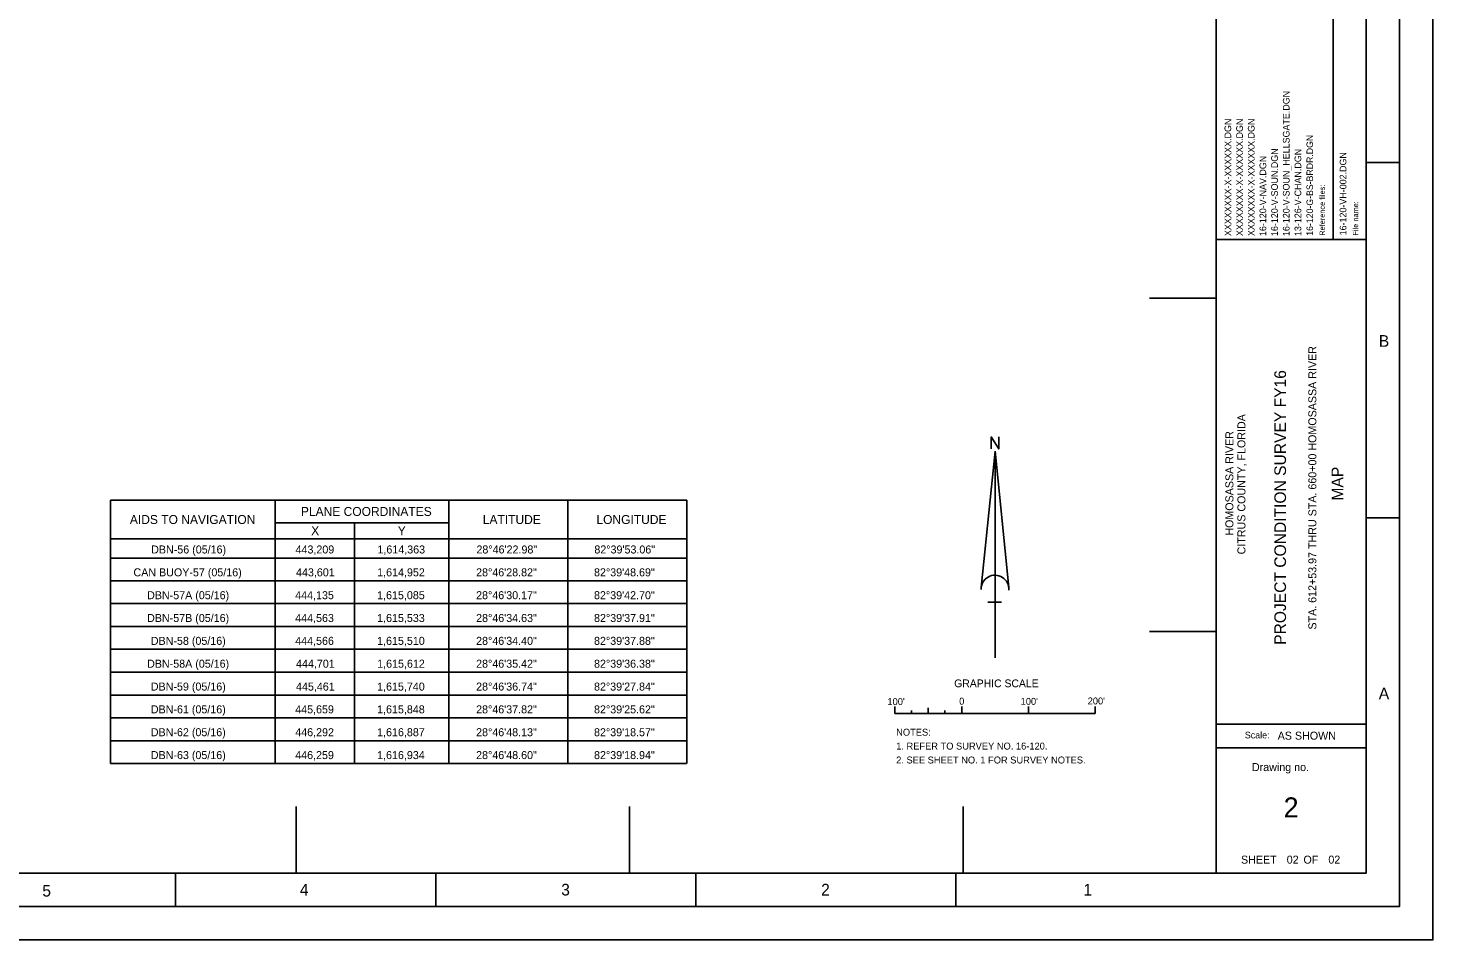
# Model space of a CAD drawing. Extents: x 442804 to 447204, y 1614037 to 1617437.
# Drawn here: x 445098 to 447204, y 1614037 to 1615405 of the extents above; entities that cross this region are included whole.
import ezdxf

# ---------------------------------------------------------------- set-up
doc = ezdxf.new("R2010")
doc.units = 0
for name, color, linetype in [('G-ANNO-NPLT', 7, 'Continuous'), ('G-ANNO-TEXT-DRWG', 7, 'Continuous'), ('G-ANNO-TEXT-PROJ', 7, 'Continuous'), ('G-ANNO-TEXT-TTLB', 7, 'Continuous'), ('G-ANNO-TTLB', 7, 'Continuous'), ('V-ANNO-NOTE', 7, 'Continuous'), ('V-ANNO-SCHD', 7, 'Continuous'), ('V-ANNO-SYMB', 7, 'Continuous'), ('V-TOPO-COOR-STAT', 7, 'Continuous')]:
    doc.layers.add(name, color=color, linetype=linetype)

msp = doc.modelspace()

# ---------------------------------------------------------------- linework, layer by layer
at = {"layer": 'G-ANNO-NPLT'}
msp.add_lwpolyline([(442804.3, 1617437.2), (447204.3, 1617437.2), (447204.3, 1614037.3), (442804.3, 1614037.3)], close=True, dxfattribs=at)
msp.add_lwpolyline([(447204.4, 1614087.3), (447204.4, 1614037.3), (447154.4, 1614037.3)], dxfattribs=at)
at = {"layer": 'G-ANNO-TTLB'}
for p, q in [((446879.3, 1617337.2), (446879.3, 1614137.3)), ((447055, 1615439.4), (447055, 1615088)), ((447154.3, 1615203.9), (447104.3, 1615203.9)), ((446879.3, 1615088), (447104.3, 1615088)), ((447154.3, 1614670.6), (447104.3, 1614670.6)), ((446879.3, 1614361), (447104.3, 1614361)), ((446879.3, 1614325.3), (447104.3, 1614325.3)), ((445319.3, 1614087.3), (445319.3, 1614137.3)), ((445709.3, 1614087.3), (445709.3, 1614137.3)), ((446099.3, 1614087.3), (446099.3, 1614137.3)), ((446489.3, 1614087.3), (446489.3, 1614137.3))]:
    msp.add_line(p, q, dxfattribs=at)
for points in [[(442854.3, 1614087.3), (447154.3, 1614087.3), (447154.3, 1617387.2), (442854.3, 1617387.2)], [(447104.3, 1617337.2), (442979.3, 1617337.2), (442979.3, 1614137.3), (447104.3, 1614137.3)]]:
    msp.add_lwpolyline(points, close=True, dxfattribs=at)
at = {"layer": 'V-ANNO-NOTE'}
for p, q in [((446397.9, 1614376.9), (446397.9, 1614387.4)), ((446397.9, 1614376.9), (446697.9, 1614376.9)), ((446422.9, 1614376.9), (446422.9, 1614381.7)), ((446447.9, 1614376.9), (446447.9, 1614385.4)), ((446472.9, 1614376.9), (446472.9, 1614381.7)), ((446497.9, 1614376.9), (446497.9, 1614387.4)), ((446497.9, 1614376.9), (446497.9, 1614387.4)), ((446497.9, 1614376.9), (446497.9, 1614381.9)), ((446597.9, 1614376.9), (446597.9, 1614387.4)), ((446697.9, 1614376.9), (446697.9, 1614387.4))]:
    msp.add_line(p, q, dxfattribs=at)
at = {"layer": 'V-ANNO-SCHD'}
for p, q in [((445221.9, 1614696.9), (446085.9, 1614696.9)), ((445221.9, 1614696.9), (445221.9, 1614301.9)), ((445468.5, 1614696.9), (445468.5, 1614301.9)), ((445729.2, 1614696.9), (445729.2, 1614301.9)), ((445907.6, 1614696.9), (445907.6, 1614301.9)), ((446085.9, 1614301.9), (446085.9, 1614696.9)), ((445468.5, 1614663.3), (445729.2, 1614663.3)), ((445587.4, 1614663.3), (445587.4, 1614301.9)), ((445221.9, 1614639.2), (446085.9, 1614639.2)), ((445221.9, 1614610.3), (446085.9, 1614610.3)), ((445221.9, 1614576.1), (446085.4, 1614576.1)), ((445221.9, 1614541.8), (446085.4, 1614541.8)), ((445221.9, 1614507.5), (446085.4, 1614507.5)), ((445221.8, 1614473.3), (446085.4, 1614473.3)), ((445221.8, 1614439), (446085.4, 1614439)), ((445221.8, 1614404.7), (446085.4, 1614404.7)), ((445221.8, 1614370.4), (446085.4, 1614370.4)), ((445221.8, 1614336.2), (446085.4, 1614336.2)), ((445221.8, 1614301.9), (446085.4, 1614301.9))]:
    msp.add_line(p, q, dxfattribs=at)
at = {"layer": 'V-ANNO-SYMB'}
for p, q in [((446527.3, 1614565.9), (446547.9, 1614770.7)), ((446547.9, 1614460.4), (446547.9, 1614770.7)), ((446568.5, 1614565.9), (446547.9, 1614770.7)), ((446557.7, 1614544.2), (446537, 1614544.2))]:
    msp.add_line(p, q, dxfattribs=at)
msp.add_lwpolyline([(446542.2, 1614774), (446542.2, 1614792.1), (446553.4, 1614774), (446553.4, 1614792.1)], dxfattribs=at)
msp.add_arc((446547.9, 1614563.8), 20.7, 355.2984, 182.0673, dxfattribs=at)
at = {"layer": 'V-TOPO-COOR-STAT'}
for p, q in [((446779.3, 1615000), (446879.3, 1615000)), ((446779.3, 1614500), (446879.3, 1614500)), ((445500, 1614137.3), (445500, 1614237.3)), ((446000, 1614137.3), (446000, 1614237.3)), ((446500, 1614137.3), (446500, 1614237.3))]:
    msp.add_line(p, q, dxfattribs=at)

# ---------------------------------------------------------------- texts
at = {"layer": 'G-ANNO-TEXT-DRWG'}
for s, height, p in [('16-120-V-SOUN_HELLSGATE.DGN', 10, (446989.5, 1615093.4)), ('XXXXXXXX-X-XXXXXX.DGN', 10, (446902, 1615093.4)), ('XXXXXXXX-X-XXXXXX.DGN', 10, (446919.5, 1615093.4)), ('XXXXXXXX-X-XXXXXX.DGN', 10, (446937, 1615093.4)), ('16-120-V-SOUN.DGN', 10, (446972, 1615093.4)), ('13-126-V-CHAN.DGN', 10, (447007, 1615093.4)), ('16-120-VH-002.DGN', 10, (447074.7, 1615094.4)), ('16-120-V-NAV.DGN', 10, (446954.5, 1615093.4)), ('STA. 612+53.97 THRU STA. 660+00 HOMOSASSA RIVER', 12, (447029.7, 1614502.9)), ('MAP', 17.5, (447069.9, 1614696.5))]:
    msp.add_text(s, height=height, rotation=90, dxfattribs=at).set_placement(p)
for s, height, p in [('2', 30, (446980.7, 1614221.1)), (' 02          02', 12, (446980.8, 1614151.7))]:
    msp.add_text(s, height=height, dxfattribs=at).set_placement(p)
at = {"layer": 'G-ANNO-TEXT-PROJ'}
for s, height, p in [('16-120-G-BS-BRDR.DGN', 9.8, (447024.7, 1615093.8)), ('PROJECT CONDITION SURVEY FY16', 17.5, (446984.2, 1614480)), ('CITRUS COUNTY, FLORIDA', 12, (446923.3, 1614615.7)), ('HOMOSASSA RIVER', 12, (446905.3, 1614643.8))]:
    msp.add_text(s, height=height, rotation=90, dxfattribs=at).set_placement(p)
at = {"layer": 'G-ANNO-TEXT-TTLB'}
for s, p in [('Reference files:', (447042.4, 1615093.8)), ('File name:', (447092.4, 1615094.1))]:
    msp.add_text(s, height=8, rotation=90, dxfattribs=at).set_placement(p)
for s, height, p in [('Scale:', 10, (446922.4, 1614339.6)), ('AS SHOWN', 12, (446971.7, 1614337.7)), ('Drawing no.', 12, (446933.1, 1614290.6)), ('SHEET         OF', 12, (446916.7, 1614151.7))]:
    msp.add_text(s, height=height, dxfattribs=at).set_placement(p)
at = {"layer": 'G-ANNO-TTLB'}
for s, p in [('B', (447123.3, 1614927.2)), ('A', (447123.3, 1614398.5)), ('4', (445505.6, 1614103.9)), ('3', (445897.5, 1614103.9)), ('2', (446287.2, 1614103.9)), ('1', (446680.4, 1614103.9)), ('5', (445119.5, 1614102.3))]:
    msp.add_text(s, height=17.5, dxfattribs=at).set_placement(p)
at = {"layer": 'V-ANNO-NOTE'}
for s, height, p in [('GRAPHIC SCALE', 11.666, (446486.7, 1614416.4)), ("100'", 10.42, (446386.6, 1614389.7)), ('0', 10.4, (446494.2, 1614390.3)), ("100'", 10.42, (446586.3, 1614390)), ("200'", 10.42, (446686.8, 1614390.6)), ('NOTES:', 10.42, (446399.7, 1614343.7)), ('1. REFER TO SURVEY NO. 16-120.', 10.416, (446399.7, 1614322.9)), ('2. SEE SHEET NO. 1 FOR SURVEY NOTES.', 10.416, (446399.7, 1614302))]:
    msp.add_text(s, height=height, dxfattribs=at).set_placement(p)
at = {"layer": 'V-ANNO-SCHD'}
for s, height, p in [('AIDS TO NAVIGATION', 13.471, (445250.8, 1614661.3)), ('PLANE COORDINATES', 13.471, (445507.2, 1614673.4)), ('LATITUDE', 13.47, (445779.9, 1614661.3)), ('LONGITUDE', 13.47, (445950.3, 1614661.3)), ('X', 13.5, (445522.6, 1614644.5)), ('Y', 13.5, (445652.4, 1614644.5))]:
    msp.add_text(s, height=height, rotation=0.0001, dxfattribs=at).set_placement(p)
at = {"layer": 'V-ANNO-SYMB'}
for s, p in [('DBN-56 (05/16)', (445282.7, 1614617.1)), ('443,209', (445499.2, 1614617.1)), ('1,614,363', (445622, 1614617.1)), ('28%%D46\'22.98"', (445770.4, 1614617.1)), ('82%%D39\'53.06"', (445947.2, 1614617.1)), ('CAN BUOY-57 (05/16)', (445256.2, 1614582.8)), ('443,601', (445499.9, 1614582.8)), ('1,614,952', (445621.6, 1614582.8)), ('28%%D46\'28.82"', (445769.9, 1614582.8)), ('82%%D39\'48.69"', (445946.7, 1614582.8)), ('DBN-57A (05/16)', (445276.6, 1614548.5)), ('444,135', (445498.7, 1614548.5)), ('1,615,085', (445621.5, 1614548.5)), ('28%%D46\'30.17"', (445769.9, 1614548.5)), ('82%%D39\'42.70"', (445946.7, 1614548.5)), ('DBN-57B (05/16)', (445276.6, 1614514.3)), ('444,563', (445498.7, 1614514.3)), ('1,615,533', (445621.5, 1614514.3)), ('28%%D46\'34.63"', (445769.9, 1614514.3)), ('82%%D39\'37.91"', (445946.7, 1614514.3)), ('DBN-58 (05/16)', (445282.2, 1614480)), ('444,566', (445498.7, 1614480)), ('1,615,510', (445621.5, 1614480)), ('28%%D46\'34.40"', (445769.9, 1614480)), ('82%%D39\'37.88"', (445946.7, 1614480)), ('DBN-58A (05/16)', (445276.6, 1614445.7)), ('444,701', (445499.9, 1614445.7)), ('1,615,612', (445621.6, 1614445.7)), ('28%%D46\'35.42"', (445769.9, 1614445.7)), ('82%%D39\'36.38"', (445946.7, 1614445.7)), ('DBN-59 (05/16)', (445282.2, 1614411.4)), ('445,461', (445499.9, 1614411.4)), ('1,615,740', (445621.5, 1614411.4)), ('28%%D46\'36.74"', (445769.9, 1614411.4)), ('82%%D39\'27.84"', (445946.7, 1614411.4)), ('DBN-61 (05/16)', (445282.2, 1614377.2)), ('445,659', (445498.7, 1614377.2)), ('1,615,848', (445621.5, 1614377.2)), ('28%%D46\'37.82"', (445769.9, 1614377.2)), ('82%%D39\'25.62"', (445946.7, 1614377.2)), ('DBN-62 (05/16)', (445282.2, 1614342.9)), ('446,292', (445498.8, 1614342.9)), ('1,616,887', (445621.5, 1614342.9)), ('28%%D46\'48.13"', (445769.9, 1614342.9)), ('82%%D39\'18.57"', (445946.7, 1614342.9)), ('DBN-63 (05/16)', (445282.2, 1614308.6)), ('446,259', (445498.7, 1614308.6)), ('1,616,934', (445621.5, 1614308.6)), ('28%%D46\'48.60"', (445769.9, 1614308.6)), ('82%%D39\'18.94"', (445946.7, 1614308.6))]:
    msp.add_text(s, height=12, dxfattribs=at).set_placement(p)

doc.saveas('drawing.dxf')
